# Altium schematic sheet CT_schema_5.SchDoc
size 218 x 258 mm
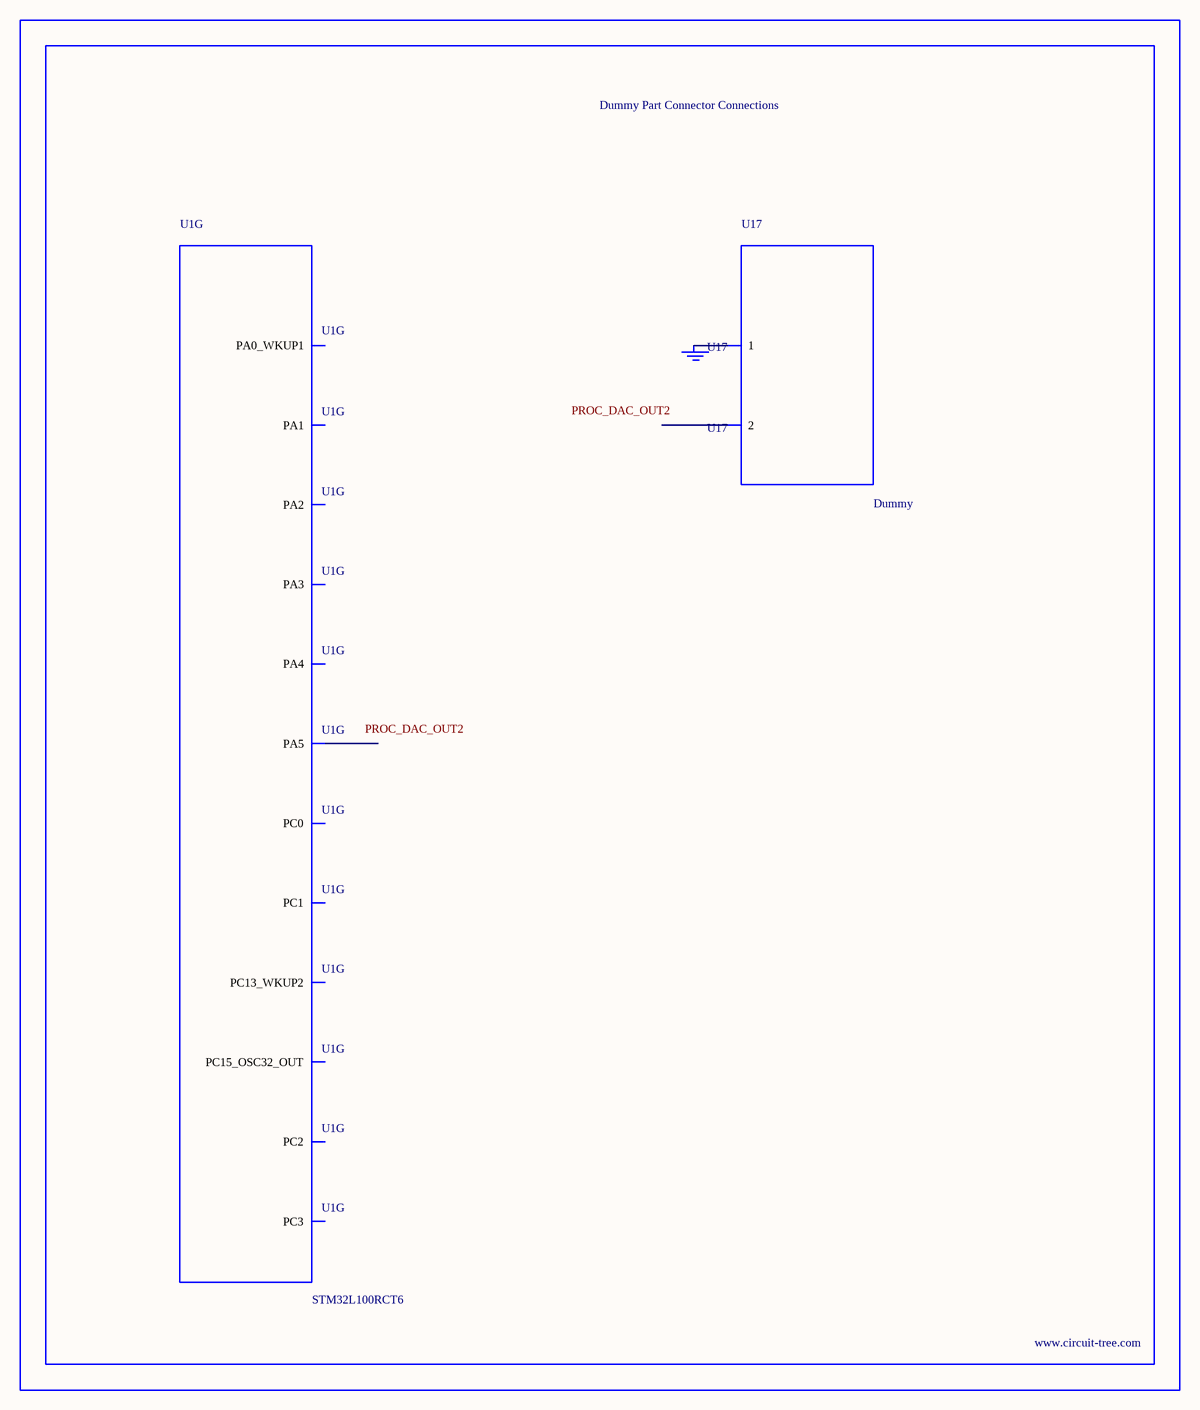
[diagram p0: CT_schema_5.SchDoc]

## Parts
BORDER4  (no value)
GND_INSTANCE_4_0  (no value)
U1  STM32L100RCT6  [LQFP64]  (part G of 7)
U17  Dummy  [DUMMY_PACKAGE_156]

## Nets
NetGND_INSTANCE_4_0_0: GND_INSTANCE_4_0.0(GND) U17.1

Not connected (* = marked no-connect by the designer): U1 2(PC13_WKUP2) 4(PC15_OSC32_OUT) 8(PC0) 9(PC1) 10(PC2) 11(PC3) 14(PA0_WKUP1) 15(PA1) 16(PA2) 17(PA3) 20(PA4) 21(PA5); U17 2

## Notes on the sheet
- Labels drawn without touching a wire or pin: PROC_DAC_OUT2

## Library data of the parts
BORDER4 = BORDER_PAGE4
GND_INSTANCE_4_0 = GND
